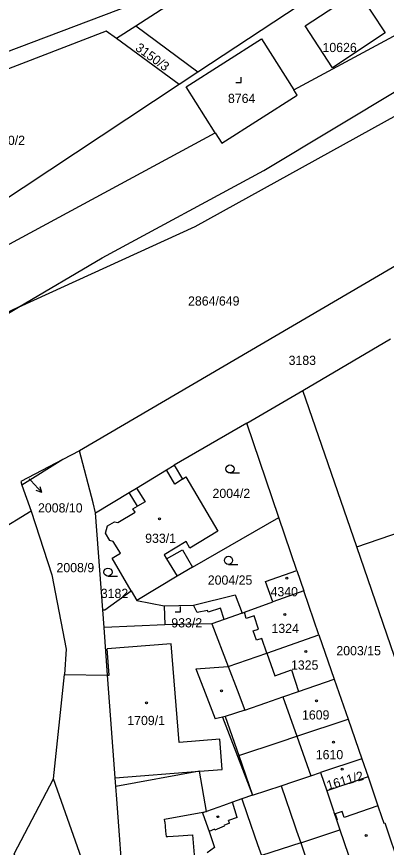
# Model space of a CAD drawing. Extents: x -564952 to -564307, y -1202373 to -1201847.
# Drawn here: x -564479.9 to -564411.7, y -1202091.3 to -1201937.9 of the extents above; entities that cross this region are included whole.
import ezdxf

# ---------------------------------------------------------------- set-up
doc = ezdxf.new("R2010")
doc.units = 0
for name, color, linetype in [('Hranice parcel', 7, 'Continuous'), ('Parcelní čísla', 7, 'Continuous'), ('Pop  PČ popisy', 7, 'Continuous'), ('Vnitřní kresba', 7, 'Continuous'), ('Značky budov', 7, 'Continuous'), ('Značky kultur', 7, 'Continuous')]:
    doc.layers.add(name, color=color, linetype=linetype)

msp = doc.modelspace()

# ---------------------------------------------------------------- linework, layer by layer
at = {"layer": 'Hranice parcel'}
for p, q in [((-564457.9, -1201939.66), (-564461.46, -1201941.96)), ((-564446.42, -1201948.18), (-564457.9, -1201939.66)), ((-564449.87, -1201950.46), (-564461.46, -1201941.96)), ((-564446.42, -1201948.18), (-564449.87, -1201950.46)), ((-564449.87, -1201950.46), (-564494.86, -1201980.19)), ((-564499.17, -1201989.59), (-564443.23, -1201959.33)), ((-564403.97, -1201980.4), (-564468.28, -1202018.06)), ((-564479.51, -1201991.57), (-564490.82, -1201996.75)), ((-564427.05, -1202006.92), (-564410.93, -1201997.4)), ((-564437.42, -1202012.99), (-564427.05, -1202006.92)), ((-564417.13, -1202035.78), (-564427.05, -1202006.92)), ((-564437.42, -1202012.99), (-564450.8, -1202020.74)), ((-564431.52, -1202030.36), (-564437.42, -1202012.99)), ((-564468.28, -1202018.06), (-564471.33, -1202019.66)), ((-564471.33, -1202019.66), (-564478.89, -1202024.39)), ((-564478.89, -1202024.39), (-564477.18, -1202029.23)), ((-564465.33, -1202029.52), (-564459.14, -1202025.77)), ((-564477.18, -1202029.23), (-564490.61, -1202037.43)), ((-564463.97, -1202047.44), (-564465.33, -1202029.52)), ((-564447.43, -1202039.56), (-564431.52, -1202030.36)), ((-564428.18, -1202040.15), (-564431.52, -1202030.36)), ((-564409.49, -1202058.02), (-564417.13, -1202035.78)), ((-564428.18, -1202040.15), (-564426.9, -1202043.9)), ((-564458.73, -1202043.91), (-564457.69, -1202045.7)), ((-564426.9, -1202043.9), (-564432.59, -1202045.97)), ((-564424.11, -1202052.05), (-564426.9, -1202043.9)), ((-564439.59, -1202044.65), (-564438.28, -1202048.03)), ((-564463.72, -1202050.66), (-564463.97, -1202047.44)), ((-564443.84, -1202049.99), (-564440.84, -1202057.87)), ((-564463.09, -1202059.5), (-564463.72, -1202050.66)), ((-564424.11, -1202052.05), (-564421.27, -1202060.22)), ((-564473.1, -1202078.61), (-564471.03, -1202059.34)), ((-564471.03, -1202059.34), (-564463.09, -1202059.5)), ((-564421.27, -1202060.22), (-564418.71, -1202067.61)), ((-564418.71, -1202067.61), (-564416.18, -1202074.92)), ((-564438.91, -1202074.33), (-564436.39, -1202081.67)), ((-564416.18, -1202074.92), (-564423.8, -1202077.47)), ((-564416.18, -1202074.92), (-564415.05, -1202078.24)), ((-564446.17, -1202077.23), (-564461.59, -1202080.01)), ((-564444.84, -1202084.65), (-564446.17, -1202077.23)), ((-564425.59, -1202078.07), (-564423.8, -1202077.47)), ((-564423.8, -1202077.47), (-564422.67, -1202080.83)), ((-564415.05, -1202078.24), (-564422.67, -1202080.83)), ((-564436.39, -1202081.67), (-564431.09, -1202079.9)), ((-564436.39, -1202081.67), (-564438.3, -1202082.34)), ((-564459.79, -1202103), (-564461.05, -1202087.35)), ((-564420.25, -1202088.03), (-564416.99, -1202097.64)), ((-564427.46, -1202090.41), (-564424.23, -1202100.06))]:
    msp.add_line(p, q, dxfattribs=at)
for points in [[(-564328.21, -1201853.59), (-564368.6, -1201879.82), (-564418.44, -1201912.36), (-564448.23, -1201931.71), (-564529.16, -1201962.4)], [(-564348.82, -1201871.01), (-564402.54, -1201903.93), (-564457.9, -1201939.66)], [(-564341.58, -1201883.31), (-564399.74, -1201917.34), (-564446.42, -1201948.18)], [(-564428.74, -1201951.43), (-564393.56, -1201932.42), (-564314.65, -1201888.26)], [(-564479.51, -1201991.57), (-564446.91, -1201976.65), (-564359.6, -1201928.27)], [(-564426.66, -1201939.6), (-564416.96, -1201933.2), (-564411.87, -1201940.91), (-564421.6, -1201947.33), (-564426.66, -1201939.6)], [(-564479.51, -1201991.57), (-564464.1, -1201982.45), (-564434.29, -1201966.3), (-564383.08, -1201935.53)], [(-564461.46, -1201941.96), (-564463.36, -1201940.57), (-564498.95, -1201954.33), (-564512.2, -1201972.88), (-564507.01, -1201978.45), (-564501.74, -1201973.64), (-564494.86, -1201980.19)], [(-564443.23, -1201959.33), (-564448.62, -1201950.87), (-564434.71, -1201942.01), (-564428.74, -1201951.43)], [(-564443.23, -1201959.33), (-564442.01, -1201961.25), (-564428.12, -1201952.41), (-564428.74, -1201951.43)], [(-564490.82, -1201996.75), (-564486.65, -1201995.79), (-564479.51, -1201991.57)], [(-564465.33, -1202029.52), (-564465.75, -1202027.69), (-564468.28, -1202018.06)], [(-564471.33, -1202019.66), (-564479.12, -1202023.74), (-564478.89, -1202024.39)], [(-564459.14, -1202025.77), (-564457.77, -1202024.94), (-564452.21, -1202021.57), (-564450.8, -1202020.74)], [(-564450.8, -1202020.74), (-564449.25, -1202023.27), (-564448.68, -1202022.89), (-564442.78, -1202032.89), (-564447.94, -1202036.01)], [(-564458.73, -1202043.91), (-564462.25, -1202037.9), (-564460.72, -1202036.98), (-564462.06, -1202034.79), (-564462.7, -1202034.64), (-564463.48, -1202033.26), (-564463.13, -1202031.94), (-564461.84, -1202031.18), (-564461.19, -1202031.3), (-564458.02, -1202029.39), (-564458.41, -1202028.77), (-564457.6, -1202028.31), (-564459.14, -1202025.77)], [(-564477.18, -1202029.23), (-564473.35, -1202040.99), (-564470.75, -1202054.71), (-564471.03, -1202059.34)], [(-564417.13, -1202035.78), (-564404.38, -1202031.4), (-564402.49, -1202037.11), (-564404.61, -1202037.8), (-564399, -1202054.61)], [(-564447.94, -1202036.01), (-564448.6, -1202034.83), (-564452.67, -1202037.25)], [(-564452.67, -1202037.25), (-564452.2, -1202038), (-564449.3, -1202036.37), (-564447.43, -1202039.56)], [(-564447.43, -1202039.56), (-564450.23, -1202041.18), (-564457.69, -1202045.7)], [(-564432.59, -1202045.97), (-564433.95, -1202042.21), (-564428.18, -1202040.15)], [(-564463.97, -1202047.44), (-564463.59, -1202047.41), (-564458.73, -1202043.91)], [(-564457.69, -1202045.7), (-564452.64, -1202046.68), (-564447.24, -1202046.59), (-564439.59, -1202044.65)], [(-564438.28, -1202048.03), (-564437.84, -1202047.87), (-564432.59, -1202045.97)], [(-564438.28, -1202048.03), (-564441.59, -1202049.19), (-564443.84, -1202049.99)], [(-564443.84, -1202049.99), (-564452.56, -1202050.17), (-564463.72, -1202050.66)], [(-564440.84, -1202057.87), (-564433.71, -1202055.4), (-564424.11, -1202052.05)], [(-564440.84, -1202057.87), (-564439.18, -1202062.21), (-564437.78, -1202065.92)], [(-564461.59, -1202080.01), (-564461.7, -1202078.41), (-564462.49, -1202067.67), (-564463.09, -1202059.5)], [(-564437.78, -1202065.92), (-564433.9, -1202064.57), (-564430.75, -1202063.48), (-564427.86, -1202062.5), (-564421.27, -1202060.22)], [(-564437.78, -1202065.92), (-564441.39, -1202067.14), (-564438.91, -1202074.33)], [(-564438.91, -1202074.33), (-564431.27, -1202071.8), (-564428.17, -1202070.77), (-564418.71, -1202067.61)], [(-564471.12, -1202112.99), (-564472.91, -1202112.19), (-564480.33, -1202092.49), (-564473.1, -1202078.61)], [(-564471.12, -1202112.99), (-564459.11, -1202118.17), (-564473.1, -1202078.61)], [(-564431.09, -1202079.9), (-564428.76, -1202079.13), (-564425.59, -1202078.07)], [(-564415.05, -1202078.24), (-564413.23, -1202083.63), (-564412.56, -1202085.59)], [(-564461.05, -1202087.35), (-564461.41, -1202082.39), (-564461.59, -1202080.01)], [(-564431.09, -1202079.9), (-564428.53, -1202087.31), (-564428.23, -1202088.2), (-564427.46, -1202090.41)], [(-564422.67, -1202080.83), (-564421.43, -1202084.51), (-564421.35, -1202084.76)], [(-564438.3, -1202082.34), (-564440.05, -1202082.96), (-564441.73, -1202083.55), (-564444.84, -1202084.65)], [(-564438.3, -1202082.34), (-564437.33, -1202085.18), (-564435.44, -1202090.73), (-564434.73, -1202092.8)], [(-564444.84, -1202084.65), (-564445.61, -1202084.93), (-564444.62, -1202087.67), (-564444.37, -1202088.37)], [(-564421.35, -1202084.76), (-564420.86, -1202086.21), (-564420.25, -1202088.03)], [(-564412.56, -1202085.59), (-564412.16, -1202086.79), (-564411.96, -1202086.73), (-564409.17, -1202094.97)], [(-564444.37, -1202088.37), (-564443.39, -1202091.32), (-564444.71, -1202092.27)]]:
    msp.add_lwpolyline(points, dxfattribs=at)
at = {"layer": 'Pop  PČ popisy'}
for p, q in [((-564477.59, -1202023.24), (-564477.27, -1202023.57)), ((-564477.27, -1202023.57), (-564475.22, -1202025.77)), ((-564475.22, -1202025.77), (-564476.27, -1202025.37)), ((-564475.22, -1202025.77), (-564475.54, -1202024.69))]:
    msp.add_line(p, q, dxfattribs=at)
at = {"layer": 'Vnitřní kresba'}
for p, q in [((-564450.71, -1202024.23), (-564452.21, -1202021.57)), ((-564449.25, -1202023.27), (-564450.71, -1202024.23)), ((-564457.77, -1202024.94), (-564456.17, -1202027.51)), ((-564456.17, -1202027.51), (-564457.6, -1202028.31)), ((-564452.2, -1202038), (-564450.23, -1202041.18)), ((-564452.64, -1202046.68), (-564452.56, -1202050.17)), ((-564446.59, -1202047.92), (-564447.24, -1202046.59)), ((-564444.69, -1202047.52), (-564446.59, -1202047.92)), ((-564444.52, -1202047.88), (-564444.69, -1202047.52)), ((-564442.27, -1202047.09), (-564444.52, -1202047.88)), ((-564441.59, -1202049.19), (-564442.27, -1202047.09)), ((-564437.53, -1202049.02), (-564437.84, -1202047.87)), ((-564436.08, -1202048.53), (-564437.53, -1202049.02)), ((-564435.24, -1202050.97), (-564436.08, -1202048.53)), ((-564436.21, -1202051.3), (-564435.24, -1202050.97)), ((-564435.61, -1202053.02), (-564436.21, -1202051.3)), ((-564434.65, -1202052.69), (-564435.61, -1202053.02)), ((-564433.71, -1202055.4), (-564434.65, -1202052.69)), ((-564451.37, -1202053.69), (-564463.17, -1202054.64)), ((-564462.81, -1202059.48), (-564463.17, -1202054.64)), ((-564449.9, -1202071.89), (-564451.37, -1202053.69)), ((-564433.71, -1202055.4), (-564432.26, -1202059.59)), ((-564446.8, -1202058.31), (-564440.84, -1202057.87)), ((-564446.8, -1202058.31), (-564445.42, -1202061.93)), ((-564432.26, -1202059.59), (-564429.18, -1202058.53)), ((-564429.18, -1202058.53), (-564427.86, -1202062.5)), ((-564463.09, -1202059.5), (-564462.81, -1202059.48)), ((-564445.42, -1202061.93), (-564443.27, -1202067.56)), ((-564430.75, -1202063.48), (-564428.17, -1202070.77)), ((-564441.89, -1202067.25), (-564443.27, -1202067.56)), ((-564441.39, -1202067.14), (-564441.89, -1202067.25)), ((-564441.89, -1202067.25), (-564436.39, -1202081.67)), ((-564442.41, -1202071.28), (-564449.9, -1202071.89)), ((-564441.98, -1202076.91), (-564442.41, -1202071.28)), ((-564428.17, -1202070.77), (-564425.59, -1202078.07)), ((-564461.7, -1202078.41), (-564446.17, -1202077.23)), ((-564446.17, -1202077.23), (-564441.98, -1202076.91)), ((-564439.17, -1202085.79), (-564440.05, -1202082.96)), ((-564413.23, -1202083.63), (-564419.48, -1202085.74)), ((-564452.59, -1202086.05), (-564444.84, -1202084.65)), ((-564419.85, -1202084.66), (-564421.13, -1202085.09)), ((-564421.13, -1202085.09), (-564420.76, -1202086.18)), ((-564419.48, -1202085.74), (-564419.85, -1202084.66)), ((-564452.55, -1202086.54), (-564452.59, -1202086.05)), ((-564452.55, -1202086.54), (-564452.4, -1202088.31)), ((-564440.63, -1202086.8), (-564441.64, -1202087.22)), ((-564439.17, -1202085.79), (-564440.76, -1202086.29)), ((-564440.63, -1202086.8), (-564440.76, -1202086.29)), ((-564420.76, -1202086.18), (-564420.86, -1202086.21)), ((-564452.4, -1202088.31), (-564452.31, -1202089.3)), ((-564443.36, -1202087.94), (-564444.37, -1202088.37)), ((-564443.3, -1202088.09), (-564443.36, -1202087.94)), ((-564441.58, -1202087.36), (-564443.3, -1202088.09)), ((-564441.64, -1202087.22), (-564441.58, -1202087.36)), ((-564427.46, -1202090.41), (-564420.25, -1202088.03)), ((-564452.31, -1202089.3), (-564452.01, -1202089.28)), ((-564452.01, -1202089.28), (-564449.99, -1202089.15)), ((-564449.99, -1202089.15), (-564447.42, -1202088.99)), ((-564447.42, -1202088.99), (-564446.4, -1202100.73)), ((-564427.46, -1202090.41), (-564434.73, -1202092.8))]:
    msp.add_line(p, q, dxfattribs=at)
at = {"layer": 'Značky budov'}
for centre in [(-564453.51, -1202030.61), (-564430.04, -1202041.59), (-564430.41, -1202048.29), (-564426.54, -1202055.11), (-564442.09, -1202062.36), (-564455.9, -1202064.58), (-564424.56, -1202064.23), (-564421.4, -1202071.86), (-564419.82, -1202076.82), (-564442.76, -1202085.61), (-564415.38, -1202089.08)]:
    msp.add_circle(centre, 0.175, dxfattribs=at)
at = {"layer": 'Značky kultur'}
for p, q in [((-564439.46, -1201950.07), (-564438.46, -1201950.07)), ((-564438.46, -1201950.07), (-564438.46, -1201949.07)), ((-564440.49, -1202022.16), (-564438.74, -1202022.1)), ((-564440.79, -1202039.04), (-564439.04, -1202039.04)), ((-564463.03, -1202041.21), (-564461.28, -1202041.21)), ((-564449.63, -1202047.78), (-564449.63, -1202046.78)), ((-564450.63, -1202047.78), (-564449.63, -1202047.78))]:
    msp.add_line(p, q, dxfattribs=at)
for centre in [(-564440.52, -1202021.41), (-564440.79, -1202038.29), (-564463.03, -1202040.46)]:
    msp.add_circle(centre, 0.75, dxfattribs=at)

# ---------------------------------------------------------------- texts
at = {"layer": 'Parcelní čísla'}
for s, rotation, p in [('3150/3', 324, (-564458.12, -1201943.99)), ('1611/2', 16, (-564422.41, -1202080.7))]:
    msp.add_text(s, height=1.7, rotation=rotation, dxfattribs=at).set_placement(p)
for s, p in [('10626', (-564423.45, -1201944.45)), ('8764', (-564440.89, -1201953.85)), ('3150/2', (-564485.28, -1201961.59)), ('2864/649', (-564448.25, -1201991.25)), ('3183', (-564429.7, -1202002.21)), ('2004/2', (-564443.74, -1202026.77)), ('2008/10', (-564475.93, -1202029.45)), ('933/1', (-564456.16, -1202035.06)), ('2008/9', (-564472.52, -1202040.48)), ('2004/25', (-564444.61, -1202042.78)), ('3182', (-564464.35, -1202045.24)), ('4340', (-564433.03, -1202044.93)), ('933/2', (-564451.34, -1202050.67)), ('1324', (-564432.86, -1202051.7)), ('2003/15', (-564420.89, -1202055.82)), ('1325', (-564429.26, -1202058.47)), ('1709/1', (-564459.46, -1202068.7)), ('1609', (-564427.23, -1202067.67)), ('1610', (-564424.69, -1202075))]:
    msp.add_text(s, height=1.7, dxfattribs=at).set_placement(p)

doc.saveas('drawing.dxf')
